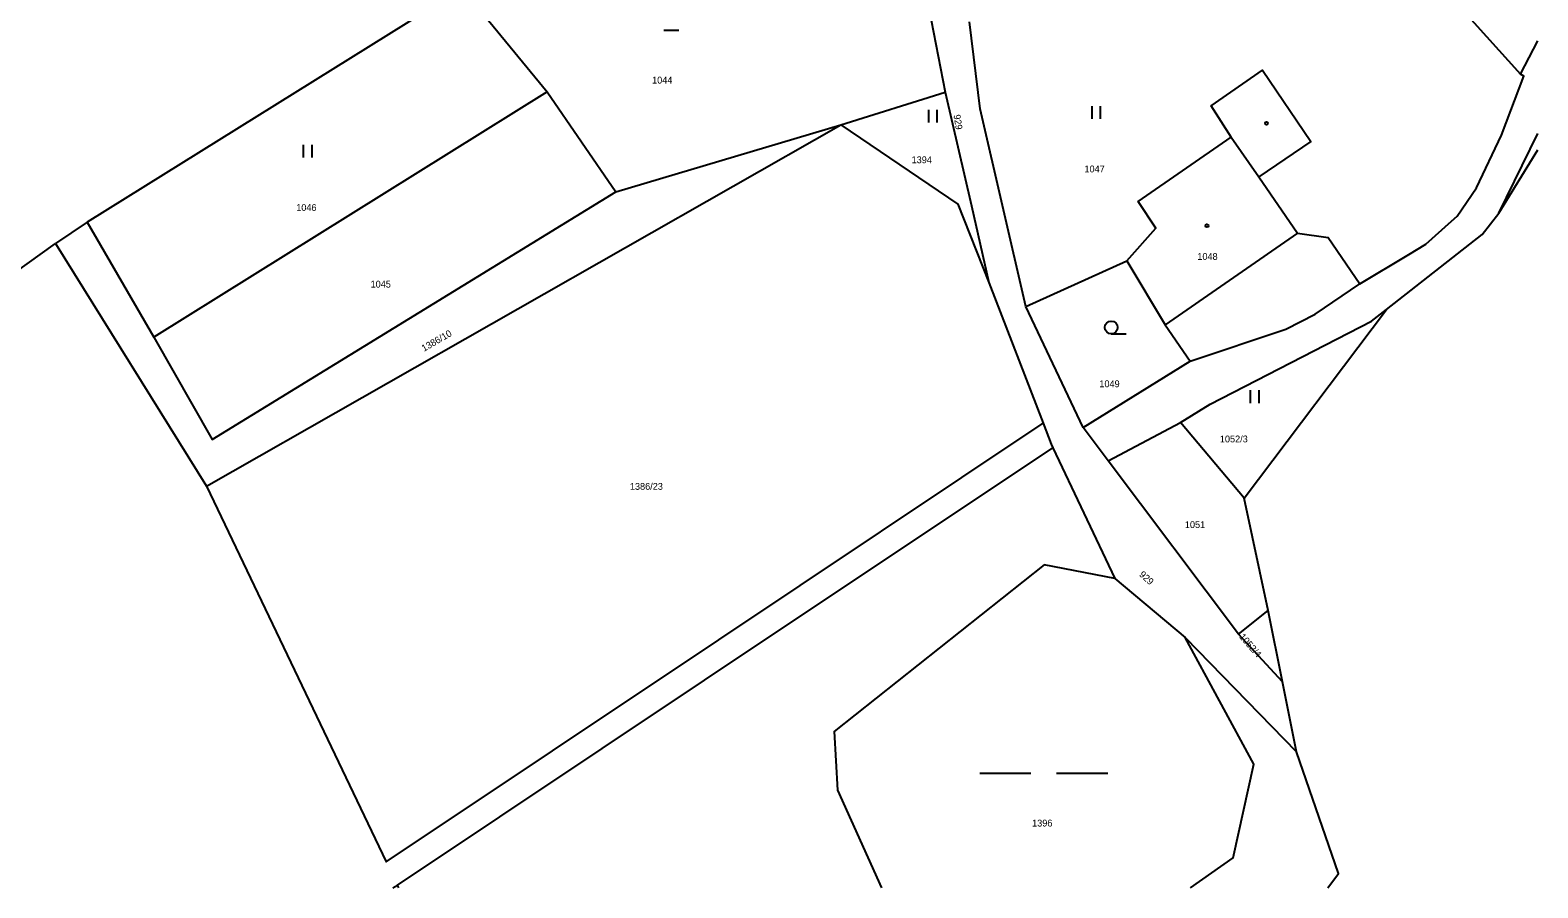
# Model space of a CAD drawing. Extents: x -719706 to -718922, y -950351 to -949651.
# Drawn here: x -719098.9 to -718922.2, y -950350.8 to -950250.4 of the extents above; entities that cross this region are included whole.
import ezdxf

# ---------------------------------------------------------------- set-up
doc = ezdxf.new("R2010")
doc.units = 0
doc.layers.add('Doplňující texty', color=7, linetype='Continuous')

msp = doc.modelspace()

# ---------------------------------------------------------------- linework, layer by layer
at = {"layer": 'Doplňující texty'}
for p, q in [((-719048.24, -950245.46), (-719038.3, -950257.58)), ((-718993.92, -950245.89), (-718991.64, -950257.64)), ((-719052.45, -950248.1), (-719092.2, -950272.85)), ((-719024.61, -950250.37), (-719022.86, -950250.37)), ((-719038.3, -950257.58), (-719084.4, -950286.32)), ((-719038.3, -950257.58), (-719030.23, -950269.29)), ((-719003.9, -950261.45), (-718991.64, -950257.64)), ((-718993.59, -950261.2), (-718993.59, -950259.7)), ((-718992.59, -950261.2), (-718992.59, -950259.7)), ((-718974.45, -950260.77), (-718974.45, -950259.27)), ((-718973.45, -950260.77), (-718973.45, -950259.27)), ((-719030.23, -950269.29), (-719003.9, -950261.45)), ((-718958.14, -950262.89), (-718954.91, -950267.55)), ((-718926.79, -950271.8), (-718922.21, -950262.47)), ((-719066.83, -950265.29), (-719066.83, -950263.79)), ((-719065.83, -950265.29), (-719065.83, -950263.79)), ((-719092.2, -950272.85), (-719095.92, -950275.34)), ((-719092.2, -950272.85), (-719084.4, -950286.32)), ((-718950.36, -950274.13), (-718965.86, -950284.86)), ((-719095.92, -950275.34), (-719078.23, -950303.75)), ((-718982.2, -950282.73), (-718970.37, -950277.38)), ((-718986.53, -950279.91), (-718980.17, -950296.39)), ((-718975.49, -950296.88), (-718982.2, -950282.73)), ((-718956.64, -950305.18), (-718939.95, -950283.09)), ((-718972.2, -950285.93), (-718970.45, -950285.93)), ((-718975.49, -950296.88), (-718962.96, -950289.13)), ((-718955.87, -950294.04), (-718955.87, -950292.54)), ((-718954.87, -950294.04), (-718954.87, -950292.54)), ((-718972.56, -950300.81), (-718975.49, -950296.88)), ((-718972.56, -950300.81), (-718964.07, -950296.32)), ((-718956.64, -950305.18), (-718964.07, -950296.32)), ((-718979.06, -950299.26), (-718971.76, -950314.57)), ((-718957.3, -950321.1), (-718972.56, -950300.81)), ((-718953.82, -950318.34), (-718956.64, -950305.18)), ((-718971.76, -950314.57), (-718963.52, -950321.47)), ((-718957.3, -950321.1), (-718953.82, -950318.34)), ((-718952.14, -950326.69), (-718953.82, -950318.34)), ((-718963.52, -950321.47), (-718950.5, -950334.88)), ((-718952.14, -950326.69), (-718957.3, -950321.1)), ((-718950.5, -950334.88), (-718952.14, -950326.69)), ((-718987.61, -950337.37), (-718981.61, -950337.37)), ((-718978.61, -950337.37), (-718972.61, -950337.37)), ((-719055.66, -950350.8), (-719055.85, -950350.47))]:
    msp.add_line(p, q, dxfattribs=at)
for points in [[(-718957.64, -950237.56), (-718941.61, -950236.22), (-718924.26, -950255.52)], [(-718982.2, -950282.73), (-718987.55, -950259.58), (-718988.8, -950249.4)], [(-718924.26, -950255.52), (-718922.21, -950251.61)], [(-718970.37, -950277.38), (-718966.96, -950273.55), (-718969.03, -950270.42), (-718958.14, -950262.89), (-718960.47, -950259.24), (-718954.46, -950255.04), (-718948.81, -950263.4), (-718954.91, -950267.55), (-718950.36, -950274.13), (-718946.78, -950274.63), (-718943.05, -950280.06)], [(-718943.05, -950280.06), (-718937.33, -950276.63), (-718935.35, -950275.44), (-718932.31, -950272.72), (-718931.68, -950272.15), (-718929.39, -950268.85), (-718926.45, -950262.67), (-718923.84, -950255.74), (-718924.26, -950255.52)], [(-718991.64, -950257.64), (-718988.59, -950270.95), (-718986.53, -950279.91)], [(-719078.23, -950303.75), (-719041.74, -950282.99), (-719003.9, -950261.45)], [(-719003.9, -950261.45), (-718990.16, -950270.73), (-718986.53, -950279.91)], [(-718926.79, -950271.8), (-718922.21, -950264.39)], [(-719084.4, -950286.32), (-719077.54, -950298.29), (-719030.23, -950269.29)], [(-718939.95, -950283.09), (-718928.74, -950274.3), (-718926.79, -950271.8)], [(-719201.14, -950350.8), (-719095.92, -950275.34)], [(-718970.37, -950277.38), (-718965.86, -950284.86), (-718962.96, -950289.13)], [(-718962.96, -950289.13), (-718951.74, -950285.38), (-718948.32, -950283.62), (-718943.05, -950280.06)], [(-718964.07, -950296.32), (-718960.62, -950294.15), (-718941.69, -950284.46), (-718939.95, -950283.09)], [(-719078.23, -950303.75), (-719057.16, -950347.74), (-719018.19, -950321.75), (-718980.17, -950296.39)], [(-718980.17, -950296.39), (-718979.22, -950298.85), (-718979.06, -950299.26)], [(-719055.85, -950350.47), (-719019.86, -950326.47), (-718979.06, -950299.26)], [(-718971.76, -950314.57), (-718980.04, -950312.96), (-719004.67, -950332.48), (-719004.29, -950339.35), (-718999.13, -950350.8)], [(-718962.91, -950350.8), (-718957.91, -950347.28), (-718955.48, -950336.3), (-718963.52, -950321.47)], [(-718946.8, -950350.8), (-718945.56, -950349.13), (-718950.5, -950334.88)], [(-719056.38, -950350.8), (-719055.85, -950350.47)]]:
    msp.add_lwpolyline(points, dxfattribs=at)
for centre, radius in [((-718954, -950261.27), 0.175), ((-718960.98, -950273.28), 0.175), ((-718972.2, -950285.18), 0.75)]:
    msp.add_circle(centre, radius, dxfattribs=at)

# ---------------------------------------------------------------- texts
for s, p in [('1044', (-719026, -950256.62)), ('1394', (-718995.59, -950265.95)), ('1047', (-718975.34, -950267.02)), ('1046', (-719067.7, -950271.54)), ('1048', (-718962.11, -950277.27)), ('1045', (-719058.99, -950280.51)), ('1049', (-718973.59, -950292.18)), ('1052/3', (-718959.47, -950298.64)), ('1386/23', (-719028.6, -950304.19)), ('1051', (-718963.57, -950308.67)), ('1396', (-718981.47, -950343.62))]:
    msp.add_text(s, height=0.8, dxfattribs=at).set_placement(p)
for s, rotation, p in [('929', 279, (-718990.68, -950260.31)), ('1386/10', 30, (-719052.73, -950288.04)), ('929', 318, (-718968.99, -950314.21)), ('1052/4', 311, (-718957.26, -950321.44))]:
    msp.add_text(s, height=0.8, rotation=rotation, dxfattribs=at).set_placement(p)

doc.saveas('drawing.dxf')
